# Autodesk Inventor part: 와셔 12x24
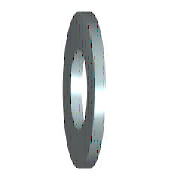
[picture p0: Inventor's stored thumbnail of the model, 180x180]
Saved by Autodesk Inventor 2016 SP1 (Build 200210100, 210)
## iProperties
IsCustomPart: 1
Created: 2012-02
Part Number: 와셔 12x24
Material: 스테인리스강
Description: 평면 와셔
Document SubType Name: Modeling
Standard: KS B 1326
Designer: mduedu
Standards Organization: KS
Language: ko-KR
Size Designation: 12x24
Categories: <MemberInstance><Categories><Category DisplayName="조임쇠" InternalName="e4da775c-781d-43d5-af7c-5136215cf5a6" Mnemonic="FSTN"><Category DisplayName="와셔" InternalN
Density: 1 g/cm^3
Appearance: 파란색 - 벽 페인트 - 광택
Author: mduedu
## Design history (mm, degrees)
sketch "스케치"
  geometry: C1 r 12 at (0, 0); C2 r 6.5 at (0, 0); 1 further point
  constraints: 2 centre point, 2 coincident
  dimensions: "d0" = 13 diameter of C2 (= SD1); "d1" = 24 diameter of C1 (= SD2)
extrude "본체" new body sketch "스케치" distance "d2" = 2.5 (= SD); taper "d3" = 0 deg
workaxis "Work Axis1"
workplane "Work Plane1"
body "Solid1"
other parameters: "SD1" = 13 [user parameter; used in 1 equation term], "SD2" = 24 [user parameter; used in 1 equation term], "SD" = 2.5 [user parameter; used in 1 equation term], "d4" = 0, "d5" = 0, "d6" = 0, "d7" = 0, "NND" = 12 [user parameter]
